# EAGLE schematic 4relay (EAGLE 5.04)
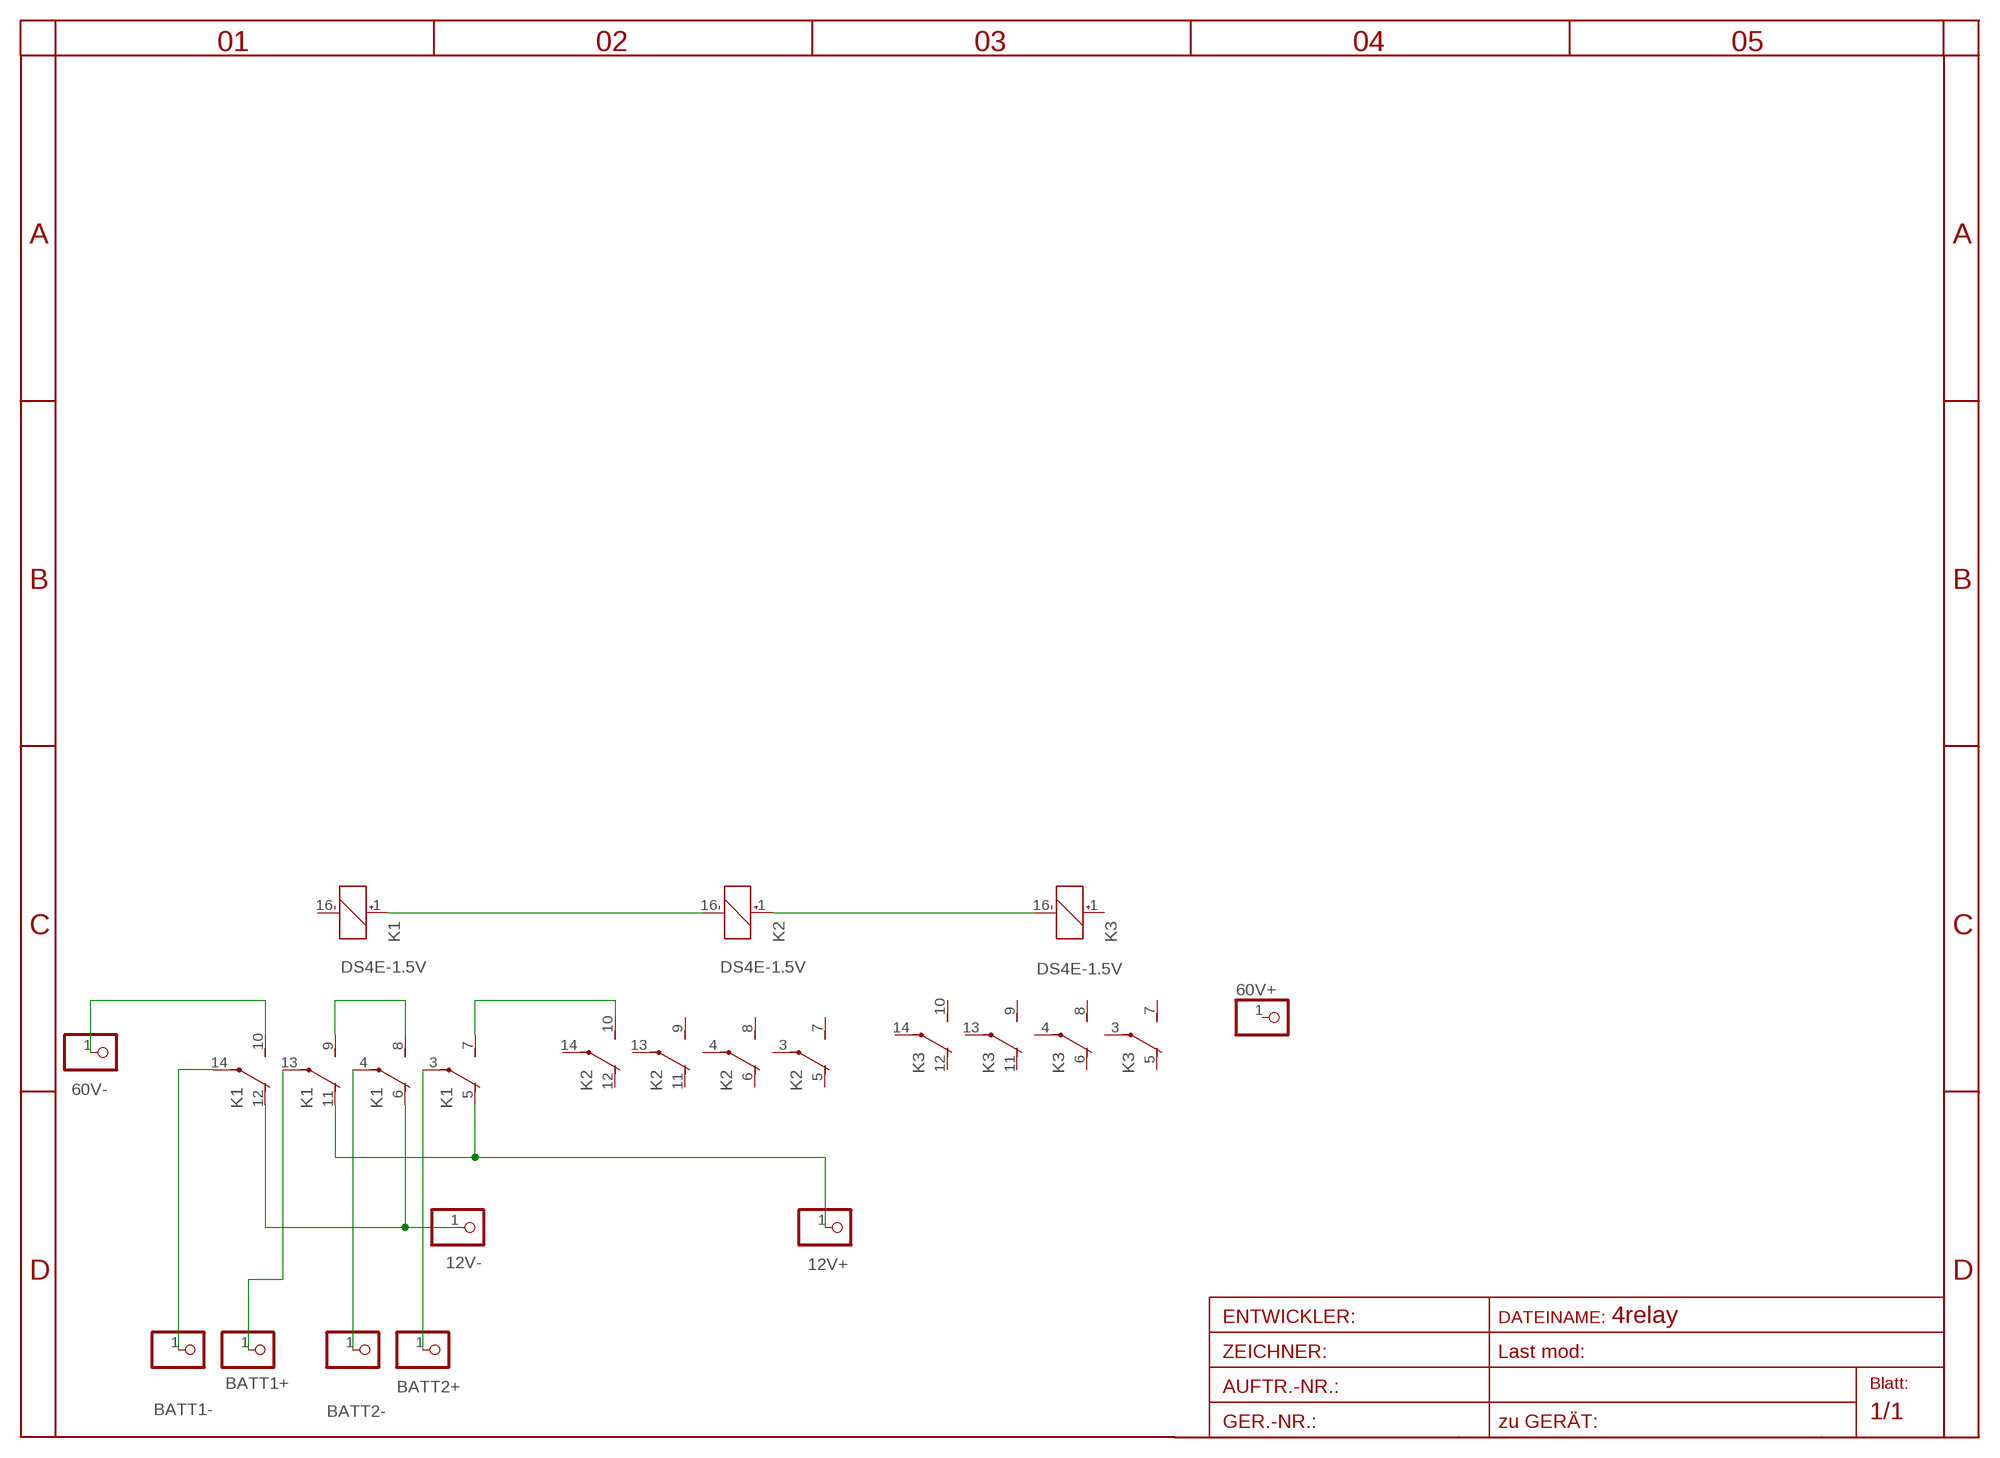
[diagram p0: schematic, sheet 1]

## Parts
12V+  PINHD-1X1  [1X01]
12V-  PINHD-1X1  [1X01]
60V+  PINHD-1X1  [1X01]
60V-  PINHD-1X1  [1X01]
BATT1+  PINHD-1X1  [1X01]
BATT1-  PINHD-1X1  [1X01]
BATT2+  PINHD-1X1  [1X01]
BATT2-  PINHD-1X1  [1X01]
K1  DS4E-1.5V  [DS4E]
K2  DS4E-1.5V  [DS4E]
K3  DS4E-1.5V  [DS4E]

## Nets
BATT1+: BATT1+.1 K1.13(4:P)
BATT1-: BATT1-.1 K1.14(5:P)
N$1: K1.1(1:+) K2.16(1:-)
N$2: K2.1(1:+) K3.16(1:-)
N$3: 60V-.1 K1.10(5:S)
N$4: K1.8(3:S) K1.9(4:S)
N$5: K1.7(2:S) K2.10(5:S)
N$6: 12V-.1 K1.6(3:O) K1.12(5:O)
N$7: 12V+.1 K1.5(2:O) K1.11(4:O)
N$10: BATT2-.1 K1.4(3:P)
N$11: BATT2+.1 K1.3(2:P)
Unconnected: 60V+.1 K1.16(1:-) K2.3(2:P) K2.4(3:P) K2.5(2:O) K2.6(3:O) K2.7(2:S) K2.8(3:S) K2.9(4:S) K2.11(4:O) K2.12(5:O) K2.13(4:P) K2.14(5:P) K3.1(1:+) K3.3(2:P) K3.4(3:P) K3.5(2:O) K3.6(3:O) K3.7(2:S) K3.8(3:S) K3.9(4:S) K3.10(5:S) K3.11(4:O) K3.12(5:O) K3.13(4:P) K3.14(5:P)

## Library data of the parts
12V+ 12V- 60V+ 60V- BATT1+ BATT1- BATT2+ BATT2- = pinhead:PINHD-1X1: PIN HEADER
K1-K3 = relay:DS4E-?*: DS-RELAYS HIGHLY SENSITIVE 1500 V FCC SURGE NAiS WITHSTANDING MINIATURE RELAY Source: http://www.mew-europe.com/.. en_ds_61005_0001.pdf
